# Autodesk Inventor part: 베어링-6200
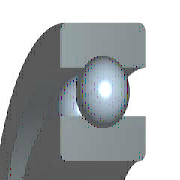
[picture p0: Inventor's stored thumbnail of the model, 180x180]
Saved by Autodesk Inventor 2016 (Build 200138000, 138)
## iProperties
Created: 2012-02
Part Number: 베어링-6200
Material: 강철, 연강
Description: 깊은 그루브 볼 베어링
Document SubType Name: Modeling
Standard: KS B 2023
Designer: mduedu
Standards Organization: KS
Language: ko-KR
Size Designation: 6200 - 10 x 30 x 9
Categories: <MemberInstance><Categories><Category DisplayName="샤프트 부품" InternalName="7f7aeb1f-a693-4053-b835-cee3144e0d98" Mnemonic="SHFT"><Category DisplayName="베어링" Inter
Density: 1 g/cm^3
Appearance: 노란색
IsCustomPart: 1
Author: mduedu
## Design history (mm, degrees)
sketch "스케치" dims "d0" = 5.2 (= -0.26 x WD + 0.26 x BD)
  geometry: L1 (1.9, 10)-(7.1, 10); L2 (4.5, 10)-(4.5, 7.4); L3 (4.5, 10)-(4.5, 12.6); L4 (2.568, 8.26)-(0, 8.26); L5 (0, 5)-(9, 5); L6 (2.568, 11.74)-(0, 11.74); L7 (0, 15)-(9, 15); L8 (9, 5)-(9, 8.26); L9 (6.432, 8.26)-(9, 8.26); L10 (6.432, 11.74)-(9, 11.74); L11 (9, 15)-(9, 11.74); L12 (-1.4, 0)-(8.4, 0) reference; L13 (0, -0.3)-(0, 5.3) reference
  constraints: 22 end point, 4 point on line, 2 collinear, 2 perpendicular, 2 symmetric about line, 1 midpoint, 1 parallel, 14 other
  dimensions: "d9" = 10 diameter of L5 L12 (= WD); "d11" = 30 diameter of L7 L12 (= BD); "d12" = 9 distance between parallel lines of L8 L13 (= KB); "d13" = 16.52 diameter of L9 L12 (= 0.326 x BD + 0.674 x WD)
revolve "본체" stored, may be unused: angle "d6" = 90 deg
revolve "볼" stored, may be unused: angle "d7" = 90 deg
pattern_circular "IDS_ARRAYBALL[SIMPL:T]" dims angle "d3" = 360 deg
body "Solid1"
fillet "모깎기1" dims "d1" = 0.6 (= KRS)
other parameters: "WD" = 10 [user parameter; used in 5 equation terms], "BD" = 30 [user parameter; used in 5 equation terms], "KB" = 9 [user parameter; used in 1 equation term], "KRS" = 0.6 [user parameter; used in 1 equation term], "d4" = 0, "d5" = 0, "d8" = 0, "d14" = 0, "d15" = 0, "BBA" = 0 [user parameter], "BC0" = 2360000 [user parameter], "BC" = 5070000 [user parameter], "BR" = 15 (= 0.5 x BD) [user parameter], "WR" = 5 (= 0.5 x WD) [user parameter]
